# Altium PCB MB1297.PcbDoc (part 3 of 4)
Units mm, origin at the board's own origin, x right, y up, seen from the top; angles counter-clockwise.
Board outline 90.1 x 62.11 mm, 4 copper layers (Top Layer, GND, POWER+GND, Bottom Layer), stack 0.778 mm thick; 235 components, 174 nets, 1727 pads, 1 vias.
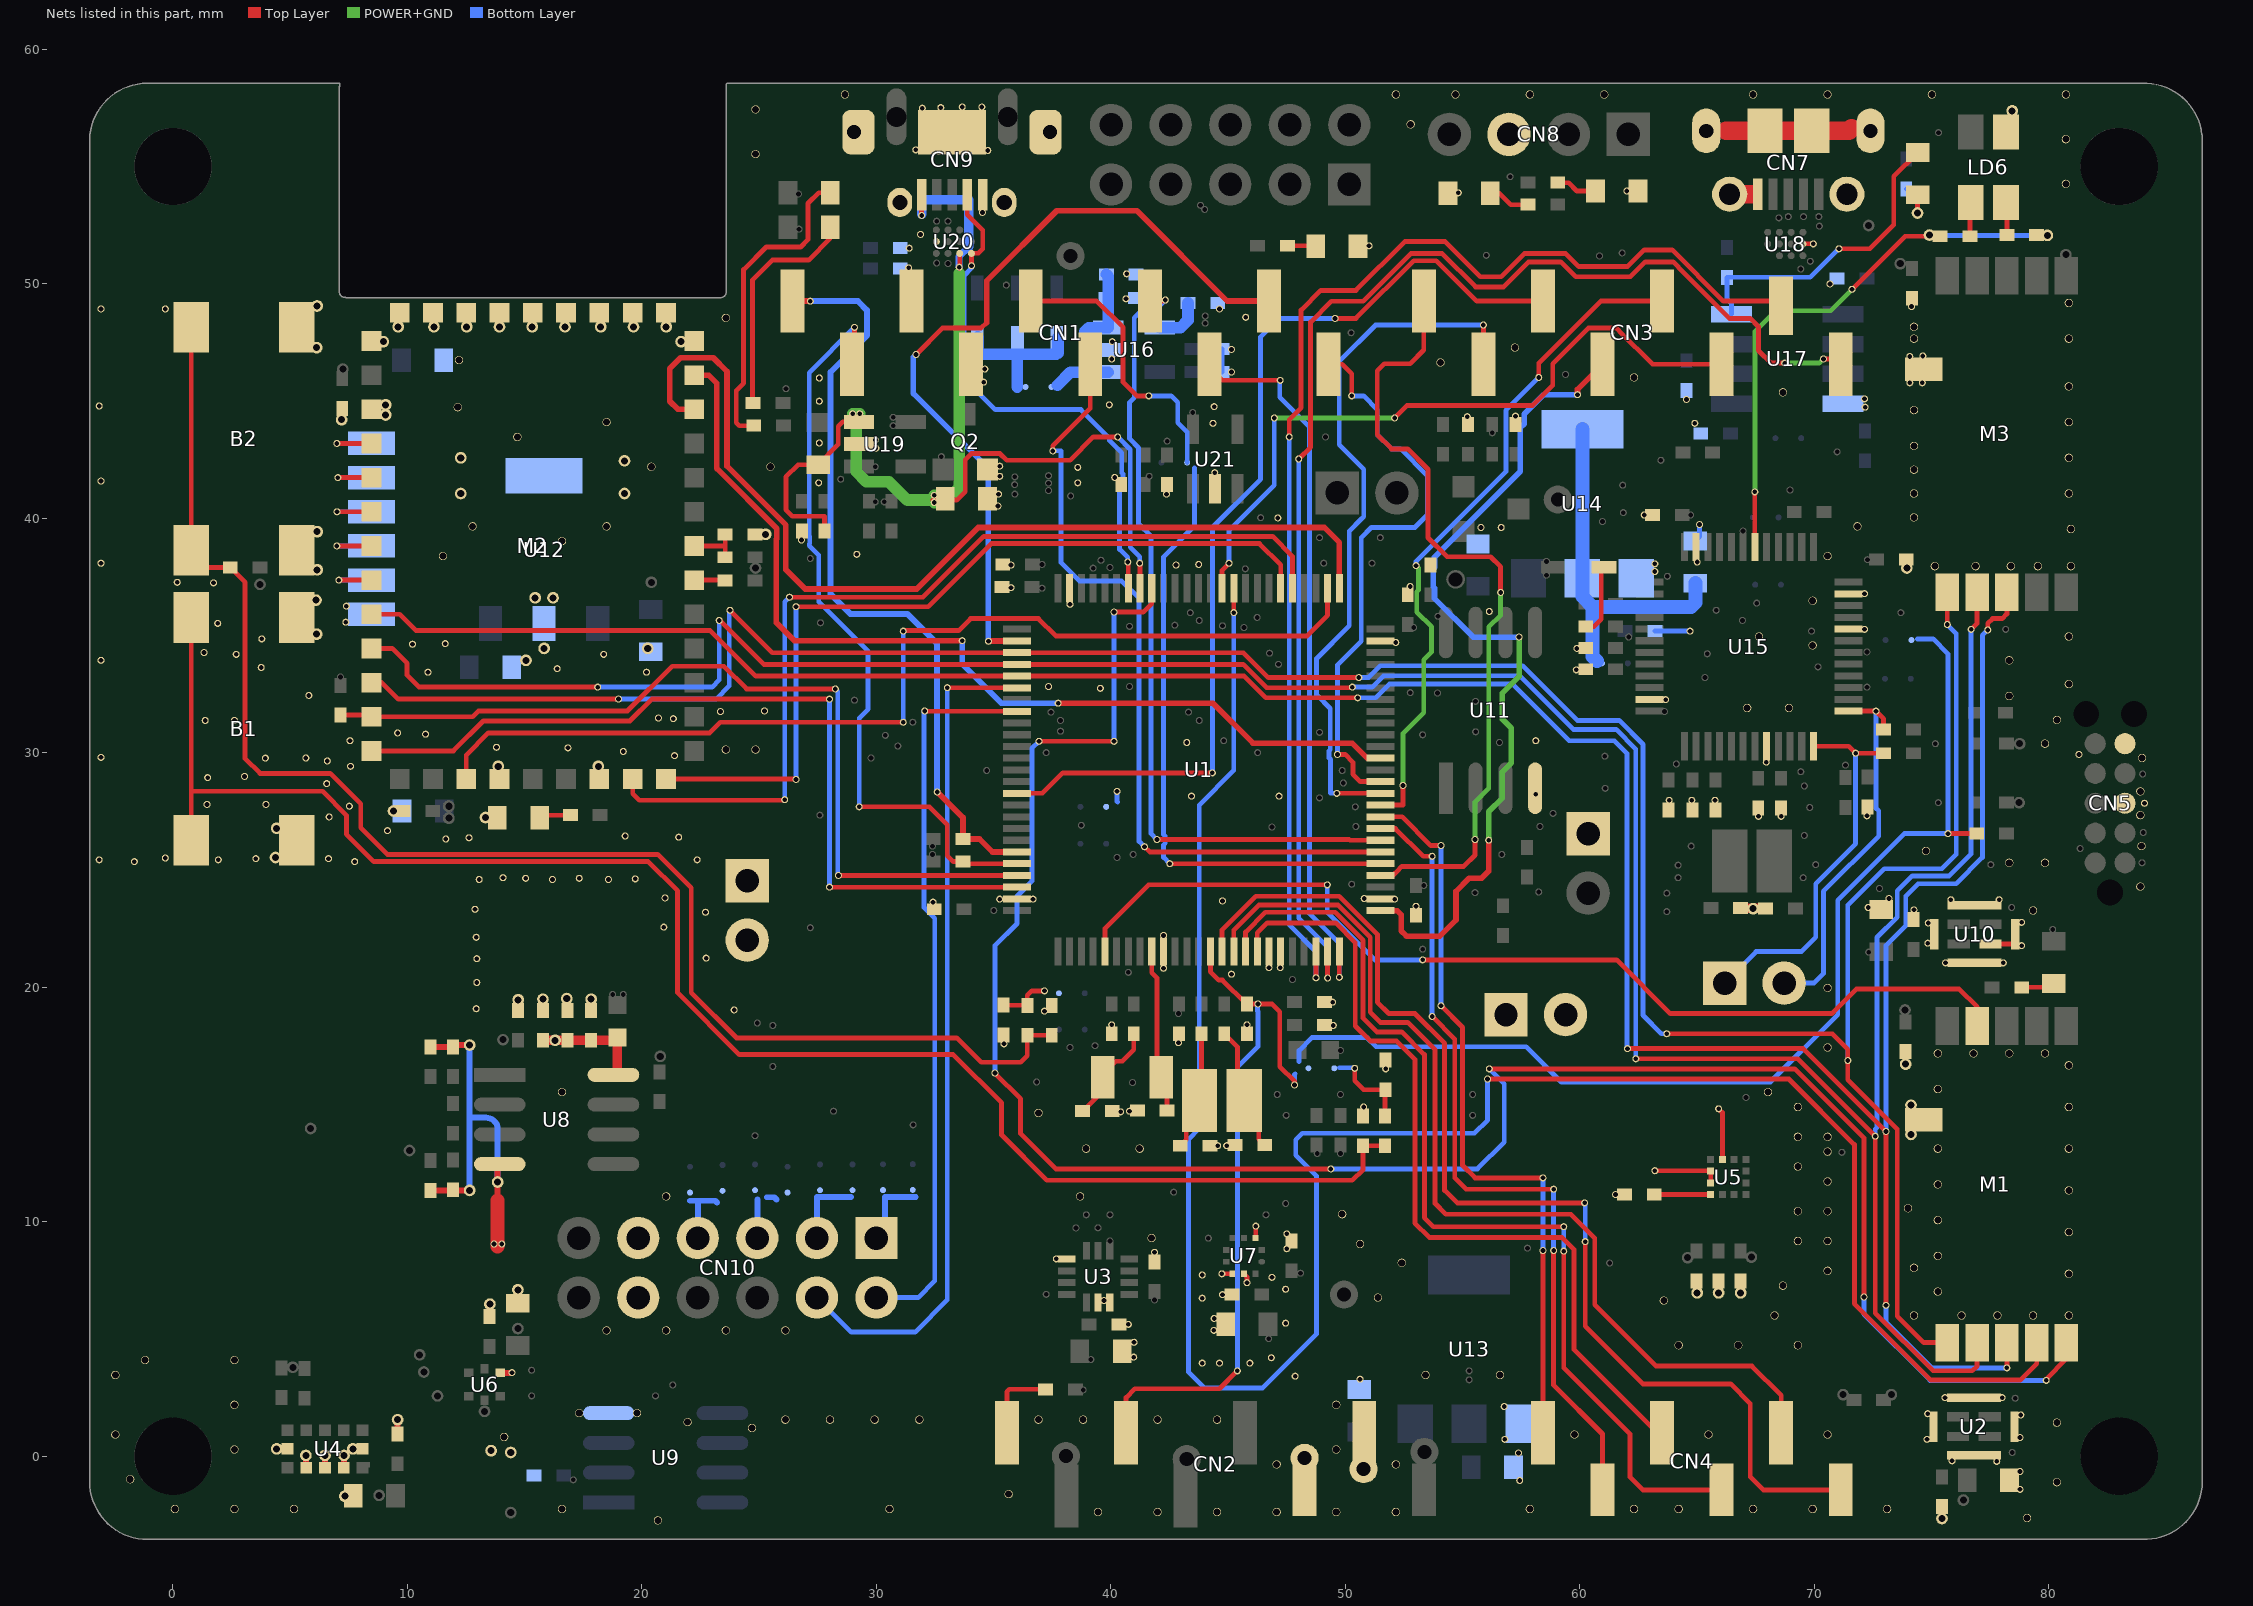
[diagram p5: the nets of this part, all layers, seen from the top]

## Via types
v1: diameter 0.4, hole 0.2, Top Layer to Bottom Layer, tented both sides, 1 vias

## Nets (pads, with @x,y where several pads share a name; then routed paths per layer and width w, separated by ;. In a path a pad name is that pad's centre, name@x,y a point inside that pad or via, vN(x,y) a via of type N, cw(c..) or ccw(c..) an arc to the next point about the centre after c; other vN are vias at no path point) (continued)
GND: B1.2 B2.2 C1.2 C2.2 C3.1 C4.2 C5.2 C6.1 C7.2 C8.1 C9.2 C10.2 C11.2 C12.2 C13.2 C14.2 C15.2 C16.2 C17.1 C18.2 C19.2 C20.2 C21.2 C22.2 C23.2 C24.2 C25.2 C26.2 C27.2 C28.2 C29.2 C30.2 C31.2 C32.2 C33.2 C34.2 C35.2 C36.2 C37.2 C38.2 C39.2 C40.2 C41.2 C42.2 C43.2 C44.2 C45.2 C46.2 C47.2 C48.2 C49.2 C50.2 C51.1 C52.1 C53.2 C54.2 C55.2 C56.2 C57.2 C58.2 C59.2 C60.2 C61.2 C62.2 C63.2 C64.2 C65.2 C66.2 C67.2 C68.2 C69.2 C71.2 C72.2 C73.2 C74.2 C75.2 C76.2 CN1.7 CN2.6 CN2.7 CN5.3 CN5.5 CN7.5 CN7.6 CN7.7 CN7.8 CN7.9 CN7.10 CN7.11 CN8.3 CN9.5 CN9.6 CN9.7 CN9.8 CN9.9 CN9.10 CN10.5 CN10.11 JP6.1 JP6.2 JP7.1 JP7.2 JP8.1 LD1.K LD2.K LD3.K LD5.K LD6.1 M1.6 M2.1 M2.3 M2.17 M2.20 M2.35 M2.36 M2.37 M2.38 M2.39 M2.40 M2.41 M2.42 M2.43 M2.44 M3.6 pad.0@13.569,0.233 pad.0@-3.068,48.925 pad.1@14.407,0.157 pad.1@-0.325,48.925 pad.2@13.518,6.482 pad.2@14.712,7.091 pad.2@-3.144,25.43 pad.3@13.328,27.234 pad.3@-0.325,25.506 pad.4@-1.646,25.354 pad.5@7.333,-1.71 pad.5@63.658,32.263 pad.5@-3.068,29.799 pad.6@7.397,36.251 pad.6@15.829,34.447 pad.6@72.141,36.784 pad.6@-3.068,33.939 pad.7@7.371,35.565 pad.7@7.673,0.31 pad.7@15.448,36.606 pad.7@72.141,35.26 pad.7@-3.068,38.079 pad.8@7.295,0.03 pad.8@16.21,36.606 pad.8@31.882,52.1 pad.8@67.95,29.596 pad.8@-3.068,41.585 pad.9@6.482,0.03 pad.9@12.273,42.575 pad.9@-3.144,44.785 pad.10@1.732,37.241 pad.10@5.669,0.03 pad.10@12.273,41.051 pad.10@65.004,38.13 pad.11@0.183,37.267 pad.11@4.425,0.31 pad.11@19.258,42.448 pad.11@62.743,40.137 pad.12@1.91,35.514 pad.12@9.581,1.554 pad.12@19.258,41.051 pad.13@1.478,28.935 pad.14@3.053,28.986 pad.15@1.377,31.374 pad.15@59.873,34.447 pad.15@69.957,51.7 pad.16@2.621,31.374 pad.16@8.971,47.528 pad.16@59.848,33.533 pad.17@1.326,34.269 pad.17@9.606,48.163 pad.18@2.698,34.193 pad.18@11.13,48.163 pad.19@6.558,28.681 pad.19@12.527,48.163 pad.19@74.148,49.027 pad.20@7.524,27.716 pad.20@13.924,48.163 pad.21@1.936,25.43 pad.21@15.321,48.163 pad.22@3.536,25.481 pad.22@16.718,48.163 pad.23@1.453,27.792 pad.23@18.242,48.163 pad.24@3.968,27.792 pad.24@12.654,17.531 pad.24@19.639,48.163 pad.25@6.66,27.259 pad.25@12.654,11.333 pad.25@21.036,48.163 pad.26@6.635,25.481 pad.26@13.848,11.689 pad.26@21.671,47.528 pad.27@7.752,25.354 pad.27@14.725,19.461 pad.28@13.061,24.592 pad.28@15.779,19.487 pad.28@25.278,39.311 pad.29@12.934,19.08 pad.29@16.795,19.512 pad.29@31.4,51.516 pad.30@12.959,20.198 pad.30@17.836,19.487 pad.31@12.959,21.214 pad.32@12.934,22.128 pad.33@12.883,23.322 pad.34@14.077,24.668 pad.35@15.042,24.643 pad.36@16.185,24.592 pad.37@17.328,24.643 pad.37@44.735,7.777 pad.38@18.573,24.592 pad.38@45.801,7.396 pad.39@19.716,24.617 pad.39@75.443,-2.662 pad.40@20.935,22.56 pad.41@20.986,23.805 pad.41@46.182,9.809 pad.42@9.149,26.675 pad.43@11.638,26.319 pad.43@44.76,6.888 pad.44@12.629,26.37 pad.44@44.404,5.872 pad.45@19.284,26.446 pad.45@44.392,5.364 pad.45@50.78,14.889 pad.45@84.079,27.843 pad.46@21.57,26.395 pad.46@51.72,16.515 pad.46@81.285,29.926 pad.47@22.357,25.43 pad.48@22.713,23.195 pad.48@48.264,-0.072 pad.48@50.779,-0.555 pad.49@22.738,21.239 pad.50@23.932,19.029 pad.50@40.988,4.856 pad.51@13.797,30.231 pad.51@40.975,4.221 pad.52@16.845,30.205 pad.52@40.747,5.618 pad.53@19.208,30.053 pad.54@21.392,29.875 pad.54@41.864,8.692 pad.55@20.706,31.475 pad.55@39.705,6.634 pad.55@40.264,28.351 pad.56@14.458,3.561 pad.56@21.341,31.45 pad.56@74.122,14.965 pad.57@14.026,9.047 pad.57@23.348,31.755 pad.57@37.673,8.412 pad.57@74.122,13.721 pad.58@13.696,9.047 pad.58@25.227,31.78 pad.58@73.894,16.718 pad.59@20.198,33.431 pad.59@51.008,51.618 pad.59@74.072,46.893 pad.60@16.388,33.584 pad.60@74.63,46.919 pad.61@18.369,34.193 pad.61@50.805,23.779 pad.61@74.072,45.776 pad.62@10.876,33.431 pad.62@52.101,23.754 pad.62@74.605,45.776 pad.63@11.613,34.65 pad.63@53.015,23.449 pad.63@64.547,45.064 pad.64@10.216,34.625 pad.64@40.671,50.424 pad.64@58.12,30.51 pad.64@64.902,44.048 pad.65@3.942,29.768 pad.65@40.645,49.357 pad.65@58.12,28.224 pad.65@72.141,45.09 pad.66 pad.67@5.796,32.441 pad.67@45.141,46.233 pad.68@3.764,33.634 pad.69@3.79,34.854 pad.69@46.741,20.833 pad.69@52.151,34.701 pad.70@6.584,29.647 pad.70@56.8,0.716 pad.70@65.004,6.964 pad.71@7.574,29.418 pad.71@56.774,2.113 pad.71@65.918,6.964 pad.72@7.549,30.51 pad.72@57.384,0.132 pad.72@66.858,6.964 pad.73@9.581,30.84 pad.73@57.435,-1.037 pad.74@10.775,30.79 pad.74@56.647,39.603 pad.75@39.553,32.745 pad.75@55.784,39.603 pad.76@37.343,32.822 pad.76@72.294,23.398 pad.77@73.183,23.779 pad.78@74.249,23.297 pad.80@74.859,22.738 pad.81@73.945,37.876 pad.81@74.84,21.874 pad.82@31.958,57.485 pad.82@67.391,23.347 pad.82@75.824,23.728 pad.83@32.746,57.51 pad.83@77.882,23.728 pad.84@7.193,44.201 pad.84@34.498,57.536 pad.84@78.84,22.763 pad.85@9.073,44.836 pad.85@34.752,55.682 pad.85@78.84,21.773 pad.86@9.073,44.404 pad.86@31.679,55.707 pad.86@75.596,21.036 pad.87@33.66,57.536 pad.87@78.059,21.036 pad.88@15.055,33.939 pad.88@34.524,53.04 pad.89@20.249,34.447 pad.89@34.625,46.36 pad.89@75.57,2.494 pad.90@34.575,45.801 pad.90@78.009,2.494 pad.91@9.403,27.513 pad.91@63.2,12.171 pad.91@78.807,1.757 pad.92@13.874,29.418 pad.92@65.918,14.813 pad.92@78.771,0.792 pad.93@18.141,29.418 pad.93@35.438,17.582 pad.94@4.425,26.776 pad.94@37.165,18.979 pad.95@4.374,25.532 pad.95@74.834,1.808 pad.96 pad.97@6.127,35.057 pad.97@38.258,36.327 pad.97@75.875,-0.198 pad.98 pad.99@6.152,37.8 pad.99@78.771,-0.656 pad.100 pad.101@6.127,47.274 pad.101@50.627,3.281 pad.105@47.452,7.117 pad.106@47.452,5.669 pad.106@72.243,27.31 pad.107@46.868,7.625 pad.107@67.62,27.284 pad.107@78.44,57.37 pad.108@43.896,7.726 pad.108@68.585,27.284 pad.109@43.896,6.736 pad.109@65.766,27.97 pad.110@43.896,3.967 pad.110@64.775,27.97 pad.111@44.633,3.967 pad.111@63.81,27.97 pad.112@42.245,22.204 pad.112@45.928,3.967 pad.113@42.245,20.807 pad.113@46.843,4.196 pad.114 pad.115@45.141,20.553 pad.115@49.459,19.36 pad.116@44.76,23.678 pad.116@49.484,18.369 pad.117@47.173,28.148 pad.118 pad.119 pad.120 pad.121@40.036,18.394 pad.121@43.744,38.029 pad.122 pad.123 pad.124 pad.125 pad.126@44.354,44.048 pad.126@54.818,53.878 pad.127 pad.128@35.743,37.038 pad.128@45.751,48.57 pad.129@27.564,45.979 pad.130@27.564,44.988 pad.131@27.564,43.21 pad.132@27.539,41.508 pad.133@29.164,38.46 pad.136@35.26,23.754 pad.137@36.683,23.754 pad.142 pad.143@52.761,37.089 pad.149@61.524,11.155 pad.173 pad.175 pad.217 pad.218 pad.219 pad.222 pad.225 pad.226 pad.231 pad.232 pad.233 pad.234 pad.235 pad.236 pad.237 pad.249 pad.250 pad.251 pad.252 pad.253 pad.254 pad.255 pad.256 pad.257 pad.258 pad.259 pad.260 pad.261 pad.262 pad.263 pad.264 pad.265 pad.266 pad.267 pad.268 pad.269 pad.270 pad.271 pad.272 pad.273 pad.274 pad.275 pad.276 pad.277 pad.278 pad.279 pad.280 pad.281 pad.282 pad.283 pad.284 pad.285 pad.286 pad.287 pad.288 pad.289 pad.290 pad.291 pad.292 pad.293 pad.294 pad.295 pad.296 pad.297 pad.298 pad.299 pad.300 pad.301 pad.302 pad.303 pad.304 pad.305 pad.306 pad.307 pad.308 pad.309 pad.310 pad.311 pad.312 pad.313 pad.314 pad.315 pad.316 pad.317 pad.318 pad.319 pad.320 pad.321 pad.322 pad.327 pad.328 pad.329 pad.330 pad.331 pad.332 pad.333 pad.334 pad.335 pad.336 pad.337 pad.338 pad.339 pad.340 pad.341 pad.342 pad.343 pad.344 pad.345 pad.346 pad.347 pad.348 pad.349 pad.350 pad.351 pad.352 pad.353 pad.354 pad.355 pad.356 pad.357 pad.358 pad.359 pad.360 pad.361 pad.362 pad.363 pad.364 pad.365 pad.366 pad.367 pad.368 pad.369 pad.370 pad.371 pad.372 pad.373 pad.374 pad.375 pad.376 pad.377 pad.378 pad.379 pad.380 pad.381 pad.382 pad.383 pad.384 pad.385 pad.386 pad.387 pad.388 pad.389 pad.390 pad.391 pad.392 pad.393 pad.394 pad.395 pad.396 pad.397 pad.398 pad.399 pad.400 pad.401 pad.402 pad.403 pad.404 pad.405 pad.406 pad.407 pad.408 pad.409 pad.410 pad.411 pad.412 pad.413 pad.414 pad.415 pad.416 pad.417 pad.418 pad.420 pad.421 pad.422 pad.423 pad.424 pad.425 pad.426 pad.427 pad.428 pad.429 pad.430 pad.431 pad.432 pad.433 pad.434 Q2.2 R1.1 R27.2 R29.2 R31.2 R36.2 R38.1 R41.2 R46.1 R53.1 R54.2 R59.1 R64.2 SB13.1 TP6.1 U1.10 U1.19 U1.20 U1.27 U1.49 U1.74 U1.99 U2.5 U3.1 U3.6 U3.7 U4.2 U4.3 U4.4 U4.6 U4.12 U5.2 U5.3 U5.12 U6.5 U7.3 U7.8 U7.9 U8.4 U9.4 U10.2 U10.5 U11.4 U12.2 U13.1 U14.1 U15.8 U15.20 U15.23 U15.35 U15.47 U16.2 U17.4 U18.D2 U19.2 U20.D2 U21.2 | length 39.4
  Top Layer w0.2: U10.2@77.515,21.841 78.499,21.841 78.542,21.798 U10.5@78.542,21.841
  Top Layer w0.204: pad.37@44.735,7.777 U7.8@45.174,7.777 ; U7.9@45.674,7.777 45.801,7.65 pad.38@45.801,7.396 ; U7.3@46.174,9.302 pad.41@46.174,9.801 ; pad.91@63.2,12.171 65.579,12.171 U5.3@65.579,11.654 ; pad.92@65.918,14.813 66.079,14.653 U5.12@66.079,12.654 ; U18.D2@69.526,51.701 pad.15@69.894,51.701
  Top Layer w0.254: pad.11@4.425,0.31 U4.6@4.882,0.31 ; U4.4@5.669,-0.478 pad.10@5.669,0.03 ; U4.3@6.482,-0.49 pad.9@6.482,0.03 ; U4.2@7.295,-0.478 pad.8@7.295,0.03 ; pad.7@7.673,0.31 U4.12@8.082,0.31 ; C22.2@9.581,0.945 pad.12@9.581,1.554 ; C72.2@10.978,11.333 pad.25@12.654,11.333 ; C69.2@10.978,17.455 C53.2@11.943,17.455 12.019,17.531 pad.24@12.654,17.531 ; pad.0@13.569,0.233 pad.0@13.574,0.228 ; 13.848,10.901 pad.26@13.848,11.689 13.848,12.234 cw(c14.154,12.234) U8.4@13.938,12.451 ; U6.5@13.964,3.553 14.45,3.553 pad.56@14.458,3.561
  Top Layer w0.4: C52.1@66.858,23.373 67.899,23.373 C51.1@67.925,23.347
  Top Layer w0.6: 13.848,8.946 13.848,10.901
  Top Layer w0.8: 66.248,56.52 71.481,56.52 71.582,56.621 ; CN7.7@66.39,53.818 67.341,53.818
  Bottom Layer w0.204: pad.55@40.264,28.351 40.264,27.919 40.29,27.894 ; C55.2@44.735,46.233 C59.2@44.735,47.223 ; C42.2@63.2,35.184 pad.222@64.699,35.184 ; C41.2@64.928,39.032 65.105,39.21 pad.217@65.105,39.73
  Bottom Layer w0.254: pad.25@12.654,11.333 12.654,14.432 ; pad.24@12.654,17.531 12.654,14.432 ; pad.26@13.848,11.689 13.848,13.973 ccw(c13.415,13.973) 13.721,14.28 ccw(c13.353,13.912) 13.353,14.432 12.654,14.432
LDO_3V3: C41.1 SB4.1 U14.2 U14.4 | length 15.4
  Bottom Layer w0.6: U14.4@60.106,43.794 U14.2@60.106,37.444 60.106,36.653 60.541,36.217 ; 60.737,33.914 60.541,34.109 60.541,36.217 ; C41.1@64.928,37.228 64.928,36.403 64.742,36.217 60.541,36.217
LED_STLINK: pad.18@67.464,41.123 pad.110@74.91,52.075 pad.111@79.939,52.062 pad.238 R44.1 R47.1 U15.30 | length 23.3
  Top Layer w0.204: U15.30@67.464,38.773 pad.18@67.464,41.123 ; pad.238@71.608,49.763 73.872,52.027 74.862,52.027 pad.110@74.91,52.075
  POWER+GND w0.204: pad.18@67.468,41.178 67.468,47.96 68.357,48.849 70.693,48.849 pad.238@71.608,49.763
  Bottom Layer w0.204: pad.110@74.91,52.075 74.923,52.062 pad.111@79.939,52.062
NetB1_1: B1.1 C35.1 R19.2 | length 73.2
  Top Layer w0.204: B1.1@0.778,26.268 0.778,28.351 ; B1.1@1.438,36.428 B1.1@0.778,35.768 0.778,28.351 ; R19.2@51.694,13.238 C35.1@50.754,13.238 50.754,12.222 50.297,11.765 37.267,11.765 35.337,13.695 35.337,15.067 33.279,17.124 24.161,17.124 21.519,19.766 21.519,24.109 20.274,25.354 8.565,25.354 7.397,26.522 7.397,27.335 6.381,28.351 0.778,28.351
NetB2_1: B2.1 C37.1 R23.1 R24.2 | length 63.9
  Top Layer w0.204: B2.1@0.778,48.138 B2.1@0.778,38.638 1.514,37.902 R23.1@2.444,37.902 3.079,37.267 3.079,29.748 3.714,29.113 6.711,29.113 8.006,27.818 8.006,26.802 9.148,25.66 20.68,25.66 22.103,24.236 22.103,19.766 24.034,17.836 33.432,17.836 34.473,16.794 36.149,16.794 36.438,17.082 R24.2@36.438,17.952 C37.1@37.479,17.952
NetC2_1: C2.1 R5.2 X1.2 | length 5.3
  Top Layer w0.204: C2.1@42.957,13.238 43.211,13.492 43.211,14.595 X1.2@43.785,15.169 ; X1.2@43.505,15.143 43.871,15.509 R5.2@43.871,18.013
NetC3_2: C3.2 CN2.3 pad.35@45.395,3.637 pad.36@46.271,19.283 pad.43@47.833,15.829 pad.72@75.697,26.548 R34.2 SB2.1 SB8.1 U1.14 | length 78
  Top Layer w0.204: CN2.3@40.646,1.001 40.646,2.495 41.026,2.875 44.633,2.875 pad.35@45.395,3.637 ; U1.14@44.244,21.516 44.244,20.663 44.606,20.301 44.76,20.301 45.777,19.283 C3.2@45.801,19.283 pad.36@46.271,19.283 46.868,19.283 47.199,18.952 47.199,16.616 47.833,15.981 pad.43@47.833,15.829 ; pad.72@75.697,26.548 R34.2@76.929,26.548
  Bottom Layer w0.204: pad.35@45.395,3.637 45.395,16.591 46.271,17.467 46.271,18.962 46.256,18.977 46.256,19.268 pad.36@46.271,19.283 ; pad.43@47.833,15.829 47.833,16.286 47.859,16.312 ; 48.024,16.82 48.024,17.298 48.574,17.849 50.919,17.849 51.312,17.456 57.712,17.456 59.213,15.956 68.128,15.956 70.998,18.826 70.998,23.71 73.836,26.548 pad.72@75.697,26.548 75.697,34.219 75.062,34.854 74.402,34.854
NetC4_1: C4.1 R7.2 X1.1 | length 5.4
  Top Layer w0.204: R7.2@44.836,18.013 45.405,17.444 X1.1@45.405,15.143 ; X1.1@45.685,15.169 46.309,14.544 46.309,13.518 C4.1@46.563,13.264
NetC14_1: C14.1 R12.2 X2.1 | length 4.4
  Top Layer w0.204: C14.1@38.791,14.711 39.649,15.57 X2.1@39.649,16.159 39.649,16.281 40.213,16.845 40.493,16.845 40.975,17.328 R12.2@40.975,18.013
NetC15_1: C15.1 U1.9 X2.2 | length 7
  Top Layer w0.204: U1.9@41.744,21.516 41.744,20.623 41.966,20.401 41.966,18.039 41.966,16.342 X2.2@42.149,16.159 42.398,15.911 C15.1@42.398,14.737
NetC23_1: C23.1 U5.4 | length 2.4
  Top Layer w0.204: C23.1@63.176,11.154 U5.4@65.579,11.154
NetC32_1: C32.1 C67.1 C68.1 L2.1 pad.31@16.299,17.734 U8.8 | length 4.6
  Top Layer w0.4: C67.1@15.779,17.734 C68.1@16.82,17.734 C32.1@17.836,17.734 18.839,17.734 L2.1@18.954,17.848 U8.8@18.954,16.427
NetC34_1: C34.1 pad.44@50.399,16.54 R19.1 SB2.2 | length 3.8
  Top Layer w0.204: pad.44@50.399,16.54 50.399,16.007 50.78,15.626 C34.1@51.72,15.626 51.694,15.6 R19.1@51.694,14.508
  Bottom Layer w0.204: 49.738,16.566 50.373,16.566 pad.44@50.399,16.54
NetC36_1: C36.1 pad.47@37.165,19.842 R24.1 SB3.2 | length 2.3
  Top Layer w0.204: C36.1@35.413,19.233 36.427,19.233 R24.1@36.438,19.222 36.438,19.648 36.632,19.842 pad.47@37.165,19.842
NetC56_1: C56.1 C57.1 SB10.1 U16.1 U16.3 | length 7.5
  Bottom Layer w0.5: 37.724,45.674 38.276,46.226 38.893,46.226 ; C56.1@39.807,50.398 39.893,50.312 U16.3@39.893,48.126 39.058,48.126 38.891,47.959 38.891,46.729 38.893,46.728 38.893,46.226 ; U16.1@39.893,46.226 38.893,46.226
NetC58_1: C58.1 U16.4 | length 2.1
  Bottom Layer w0.5: U16.4@42.093,48.126 42.97,48.126 43.287,48.443 C58.1@43.287,49.179
NetC66_1: C66.1 CN9.1 pad.0@31.928,52.913 pad.4@33.533,50.703 pad.20@29.291,44.455 pad.21@32.466,40.975 pad.22@32.466,40.67 pad.126@28.987,44.455 pad.179 pad.181 R57.1 R61.2 U1.68 U19.1 U20.B3 | length 49.7
  Top Layer w0.2: pad.4@33.555,50.648 U20.B3@33.555,51.295
  Top Layer w0.204: R57.1@27.788,39.451 27.788,40.086 26.421,40.086 26.142,40.365 26.142,41.762 26.663,42.283 R61.2@27.513,42.283 28.377,43.147 28.377,43.921 28.565,44.109 U19.1@29.258,44.109 ; pad.0@31.928,52.964 CN9.1@31.928,53.792 ; pad.22@32.416,40.772 33.432,40.772 33.787,41.127 33.787,42.499 34.047,42.758 35.272,42.758 35.557,42.474 38.258,42.474 39.248,43.464 pad.181@40.29,43.464 ; pad.179@41.229,38.079 41.244,38.065 U1.68@41.244,37.016
  POWER+GND w0.5: pad.126@28.987,44.455 pad.20@29.291,44.455 29.139,44.302 29.139,41.991 29.571,41.559 30.536,41.559 31.323,40.772 pad.22@32.466,40.772 ; pad.22@32.466,40.67 pad.22@32.466,40.772 ; pad.21@32.466,40.975 pad.22@32.466,40.772 ; 33.533,50.446 33.533,41.305 33,40.772 pad.22@32.466,40.772
  Bottom Layer w0.204: pad.181@40.29,43.464 40.824,42.93 40.824,41.567 40.823,41.566 40.823,38.765 41.229,38.359 pad.179@41.229,38.079
  Bottom Layer w0.3: pad.4@33.524,50.703 33.524,51.154 33.94,51.57
  Bottom Layer w0.4: pad.0@31.928,52.964 31.928,53.573 33.94,53.573 33.94,51.57
NetCN1_1: CN1.1 pad.58@50.272,45.217 pad.141@49.662,29.926 U1.37 | length 24.5
  Top Layer w0.204: CN1.1@49.282,46.561 49.867,46.561 50.272,46.157 pad.58@50.272,45.217 ; pad.141@49.662,29.926 49.992,29.926 50.323,29.596 50.323,29.088 50.645,28.766 U1.37@51.494,28.766
  Bottom Layer w0.204: pad.141@49.662,29.926 49.662,33.736 50.678,34.752 50.678,39.172 51.11,39.603 52.964,39.603 53.498,40.137 53.498,41.813 52.355,42.956 51.974,42.956 51.364,43.566 51.364,44.633 50.78,45.217 pad.58@50.272,45.217
NetCN1_2: CN1.2 pad.27@31.691,46.982 pad.95@34.778,34.752 U1.77 | length 35.1
  Top Layer w0.204: pad.27@31.691,46.982 32.825,48.115 34.476,48.115 34.702,48.341
  Top Layer w0.24: 34.702,48.341 34.702,50.119 37.694,53.112 41.107,53.112 44.957,49.261 CN1.2@46.742,49.261 ; pad.95@34.778,34.752 34.791,34.766 U1.77@35.994,34.766
  Bottom Layer w0.24: pad.27@31.691,46.982 31.577,46.868 31.577,45.318 34.778,42.118 pad.95@34.778,34.752
NetCN1_3: CN1.3 pad.23@47.222,45.879 pad.72@49.744,20.421 U1.25 | length 30.9
  Top Layer w0.204: CN1.3@44.202,46.435 44.758,45.879 pad.23@47.222,45.879 ; pad.72@49.744,20.421 U1.25@49.744,21.516
  Bottom Layer w0.204: pad.23@47.222,45.879 47.198,45.855 47.198,45.166 48.468,43.896 48.468,23.144 49.744,21.869 pad.72@49.744,20.421
NetCN1_4: CN1.4 pad.63@42.322,49.306 pad.83@41.966,26.295 U1.32 | length 34.7
  Top Layer w0.204: CN1.4@41.662,49.261 42.277,49.261 pad.63@42.322,49.306 ; pad.83@41.966,26.295 50.163,26.295 50.193,26.266 U1.32@51.494,26.266
  Bottom Layer w0.204: pad.83@41.966,26.295 41.712,26.549 41.712,39.222 41.179,39.756 41.179,43.008 40.798,43.389 40.798,44.937 41.001,45.141 41.001,48.544 41.233,48.776 41.792,48.776 pad.63@42.322,49.306
NetCN1_5: CN1.5 pad.38@37.525,42.868 pad.73@41.433,25.989 U1.31 | length 34.3
  Top Layer w0.204: pad.38@37.525,42.868 37.525,43.088 39.122,44.684 CN1.5@39.122,46.561 ; pad.73@41.433,25.989 41.656,25.766 U1.31@51.494,25.766
  Bottom Layer w0.204: pad.38@37.525,42.868 37.877,42.88 37.877,38.105 38.664,37.317 40.467,37.317 41.204,36.581 41.204,26.218 pad.73@41.433,25.989
NetCN1_6: CN1.6 pad.84@42.512,25.266 pad.171 SB1.1 U1.30 | length 38.7
  Top Layer w0.204: CN1.6@36.582,49.261 39.395,49.261 40.518,48.138 40.518,45.801 41.102,45.217 pad.171@41.619,45.217 ; pad.84@42.512,25.266 U1.30@51.494,25.266
  Bottom Layer w0.204: pad.171@41.619,45.217 42.576,45.217 42.855,44.937 42.855,44.074 43.253,43.675 SB1.1@43.253,42.372 ; pad.84@42.512,25.266 42.245,25.532 42.245,26.074 42.32,26.148 42.32,26.442 42.245,26.516 42.245,38.359 43.566,39.68 43.566,42.143
NetCN1_8: CN1.8 pad.28@31.374,50.678 R2.1
NetCN1_9: CN1.9 pad.108@29.266,27.691 pad.110@29.063,48.138 R8.2 U1.96 | length 32.6
  Top Layer w0.204: CN1.9@28.962,46.561 29.063,46.662 pad.110@29.063,48.138 ; pad.108@29.266,27.691 32.263,27.691 33.025,26.929 33.025,25.608 33.279,25.354 R8.2@33.686,25.354 ; R8.2@33.774,25.266 U1.96@35.994,25.266
  Top Layer w0.254: R8.2@33.686,25.354 R8.2@33.774,25.266
  Bottom Layer w0.204: pad.110@29.063,48.138 27.132,46.207 27.132,39.24 27.156,39.217 27.156,38.923 27.132,38.9 27.132,38.834 27.537,38.429 27.537,36.43 29.647,34.32 29.647,31.856 29.266,31.475 pad.108@29.266,27.691
NetCN1_10: CN1.10 pad.109@32.593,28.326 pad.111@27.183,49.255 R9.2 U1.95 | length 32.8
  Top Layer w0.254: CN1.10@26.422,49.261 27.177,49.261 pad.111@27.183,49.255 ; pad.109@32.593,28.326 33.686,27.234 R9.2@33.686,26.319 34.397,26.319 34.95,25.766 U1.95@35.994,25.766
  Bottom Layer w0.254: pad.111@27.183,49.255 29.215,49.255 29.596,48.874 29.596,47.782 28.047,46.233 28.047,36.759 28.885,35.92 31.323,35.92 32.593,34.65 pad.109@32.593,28.326
NetCN2_1: CN2.1 R3.2 | length 3.4
  Top Layer w0.204: CN2.1@35.566,1.001 35.566,2.749 35.667,2.85 R3.2@37.216,2.85
NetCN3_1: CN3.1 pad.25@48.011,42.524 pad.67@68.738,46.614 pad.69@70.389,46.792 pad.71@49.244,20.389 U1.24 | length 57.4
  Top Layer w0.204: pad.25@48.011,42.524 48.519,43.032 48.519,48.366 49.408,49.255 50.754,49.255 52.786,51.287 54.133,51.287 55.555,49.865 56.749,49.865 57.816,50.932 59.186,50.932 59.821,50.297 62.159,50.297 62.794,50.932 63.984,50.932 64.22,50.696 64.22,50.674 66.375,48.519 67.264,48.519 67.62,48.163 67.62,47.147 68.153,46.614 pad.67@68.738,46.614 ; pad.71@49.244,20.389 U1.24@49.244,21.516 ; pad.69@70.389,46.792 CN3.1@70.896,46.792
  POWER+GND w0.204: pad.67@68.738,46.614 70.211,46.614 pad.69@70.389,46.792
  Bottom Layer w0.204: pad.25@48.011,42.524 48.011,22.941 49.244,21.708 pad.71@49.244,20.389
NetCN3_2: CN3.2 pad.24@47.605,43.464 pad.70@48.748,20.401 U1.23 | length 54.4
  Top Layer w0.204: pad.24@47.605,43.464 47.605,44.201 48.113,44.709 48.113,48.874 48.951,49.713 50.45,49.713 52.532,51.795 54.26,51.795 55.758,50.297 56.647,50.297 57.638,51.287 59.39,51.287 59.949,50.729 62.032,50.729 62.743,51.44 63.937,51.44 66.116,49.261 CN3.2@68.586,49.261 ; U1.23@48.744,21.516 48.744,20.405 pad.70@48.748,20.401
  Bottom Layer w0.204: pad.24@47.605,43.464 47.605,22.662 48.748,21.519 pad.70@48.748,20.401
NetCN3_3: CN3.3 pad.202 pad.203 pad.204 U1.61 | length 30
  Top Layer w0.204: U1.61@44.744,37.016 44.744,37.784 pad.202@45.039,38.079 ; pad.204@52.101,44.277 52.634,44.81 57.993,44.81 58.845,45.662 58.845,46.588 60.372,48.115 61.561,48.115 61.68,47.996 61.68,47.982 63.101,46.561 CN3.3@66.046,46.561
  POWER+GND w0.204: pad.203@46.97,44.277 pad.204@52.101,44.277
  Bottom Layer w0.204: pad.202@45.039,38.079 45.039,39.476 46.97,41.407 pad.203@46.97,44.277
NetCN3_4: CN3.4 pad.224 pad.229 pad.230 U1.35 | length 29.2
  Top Layer w0.204: U1.35@51.494,27.766 52.458,27.766 pad.229@52.458,28.604 ; pad.224@58.247,46.004 58.247,46.614 60.895,49.261 CN3.4@63.506,49.261
  POWER+GND w0.204: pad.229@52.458,28.604 52.458,30.816 53.345,31.704 53.345,33.965 53.675,34.295 53.675,35.362 53.04,35.997 53.04,36.868 53.115,36.942 53.115,37.878 pad.230@53.015,37.978
  Bottom Layer w0.204: pad.230@53.015,37.952 pad.230@53.015,37.978 53.015,38.156 56.85,41.991 56.85,44.607 pad.224@58.247,46.004
NetCN3_5: CN3.5 pad.52@56.114,26.268 pad.223 pad.228 U1.26 | length 36.3
  Top Layer w0.24: U1.26@51.494,23.266 52.208,23.266 52.38,23.093 52.38,22.408 52.609,22.179 54.031,22.179 54.717,22.865 54.717,24.084 55.276,24.643 55.809,24.643 56.114,24.948 pad.52@56.114,26.268 ; pad.223@59.898,45.268 59.898,45.493 CN3.5@60.966,46.561
  POWER+GND w0.24: pad.52@56.114,26.268 56.114,27.488 56.698,28.072 56.698,29.189 57.079,29.57 57.079,31.044 56.698,31.425 56.698,32.542 57.409,33.253 pad.228@57.409,34.93
  Bottom Layer w0.24: pad.228@57.409,34.93 55.453,34.93 53.802,36.581 53.802,37.019 53.752,37.07 53.752,37.844 53.802,37.895 53.802,38.333 57.46,41.991 57.46,43.862 57.629,44.03 57.629,44.446 58.451,45.268 pad.223@59.898,45.268
NetCN3_6: CN3.6 pad.65@44.328,29.139 pad.75@49.561,48.519 U1.90 | length 42.2
  Top Layer w0.204: U1.90@35.994,28.266 37.08,28.266 37.953,29.139 pad.65@44.328,29.139 ; pad.75@49.561,48.519 50.451,48.519 52.913,50.981 53.88,50.981 55.6,49.261 CN3.6@58.426,49.261
  Bottom Layer w0.204: pad.65@44.328,29.139 44.328,39.603 46.386,41.661 46.386,47.731 47.173,48.519 pad.75@49.561,48.519
NetCN3_7: CN3.7 pad.57@55.885,48.239 pad.140@49.637,28.266 U1.36 | length 30.6
  Top Layer w0.204: pad.140@49.637,28.266 U1.36@51.494,28.266 ; pad.57@55.885,48.239 pad.57@55.885,48.239 CN3.7@55.886,46.561
  Bottom Layer w0.204: pad.140@49.637,28.266 49.367,28.266 49.367,29.721 49.308,29.779 49.308,30.073 49.356,30.121 49.356,31.884 48.774,32.466 48.774,34.017 50.17,35.412 50.17,39.451 50.667,39.948 ; 50.668,39.948 50.787,40.067 50.787,42.086 49.738,43.135 49.738,46.69 51.288,48.239 pad.57@55.885,48.239
NetCN3_8: CN3.8 pad.54@55.53,26.294 pad.55@56.622,36.835 U1.29 | length 33.6
  Top Layer w0.204: U1.29@51.494,24.766 52.033,24.766 52.298,25.031 52.298,25.043 52.405,25.151 55.047,25.151 55.53,25.633 pad.54@55.53,26.294 ; CN3.8@53.346,49.261 53.346,47.174 52.761,46.588 51.669,46.588 51.364,46.284 51.364,43.566 51.974,42.956 52.659,42.956 53.524,42.091 53.524,39.17 54.336,38.359 56.19,38.359 56.622,37.927 pad.55@56.622,36.835
  POWER+GND w0.204: pad.54@55.53,26.294 55.53,27.894 56.114,28.478 56.114,35.362 56.622,35.87 pad.55@56.622,36.835
NetCN4_1: CN4.1 pad.77@58.426,8.768 pad.81@58.426,11.866 pad.88@54.082,26.04 pad.90@54.082,19.207 U1.34 | length 31.6
  Top Layer w0.204: U1.34@51.494,27.266 52.424,27.266 53.65,26.04 pad.88@54.082,26.04 ; pad.90@54.082,19.207 54.996,18.293 54.996,12.4 55.531,11.866 pad.81@58.426,11.866 ; CN4.1@58.426,1.001 pad.77@58.426,8.768
  Bottom Layer w0.204: pad.90@54.082,19.283 pad.88@54.082,26.04 ; pad.81@58.426,11.866 pad.81@58.426,11.866 pad.77@58.426,8.768
NetCN4_2: CN4.2 pad.78@58.882,8.768 pad.82@58.882,11.384 pad.87@53.701,25.583 pad.89@53.701,18.75 U1.33 | length 34.9
  Top Layer w0.204: U1.33@51.494,26.766 52.137,26.766 53.32,25.583 pad.87@53.701,25.583 ; pad.89@53.701,18.75 54.666,17.785 54.666,11.867 55.149,11.384 pad.82@58.882,11.384 ; pad.78@58.882,8.768 58.882,3.027 60.966,0.944 CN4.2@60.966,-1.439
  Bottom Layer w0.204: pad.89@53.701,18.75 pad.87@53.701,25.583 ; pad.78@58.882,8.768 pad.82@58.882,11.384 pad.82@58.908,11.384
NetCN4_3: CN4.3 U1.18 | length 35.9
  Top Layer w0.204: U1.18@46.244,21.516 46.244,22.317 46.665,22.738 49.586,22.738 50.424,21.9 50.424,18.344 51.059,17.709 52.177,17.709 52.964,16.921 52.964,9.936 53.574,9.327 59.238,9.327 59.746,8.819 59.746,4.551 63.296,1.001 CN4.3@63.506,1.001
NetCN4_4: CN4.4 pad.75@59.314,9.784 pad.76@59.314,8.742 U1.17 | length 42.3
  Top Layer w0.204: U1.17@45.744,21.516 45.744,22.35 46.588,23.194 49.563,23.194 50.754,22.002 50.754,18.674 51.339,18.09 52.405,18.09 53.371,17.124 53.371,10.165 53.752,9.784 pad.75@59.314,9.784 ; pad.76@59.314,8.742 59.314,3.764 62.134,0.945 62.134,-0.884 62.688,-1.439 CN4.4@66.046,-1.439
  Bottom Layer w0.204: pad.76@59.314,8.742 pad.75@59.314,9.784
NetCN4_5: CN4.5 U1.16 | length 42.3
  Top Layer w0.204: U1.16@45.244,21.516 45.244,22.434 46.309,23.5 49.69,23.5 51.06,22.129 51.06,18.927 51.491,18.496 52.659,18.496 53.828,17.328 53.828,10.774 54.285,10.317 59.619,10.317 60.635,9.301 60.635,6.456 63.251,3.84 67.341,3.84 68.586,2.595 CN4.5@68.586,1.001
NetCN4_6: CN4.6 pad.79@60.229,9.149 pad.80@60.203,10.8 U1.15 | length 48.7
  Top Layer w0.204: U1.15@44.744,21.516 44.744,22.442 46.182,23.881 49.741,23.881 51.366,22.256 51.366,19.357 51.847,18.877 52.964,18.877 54.234,17.607 54.234,11.333 54.768,10.8 pad.80@60.203,10.8 ; pad.79@60.229,9.149 60.229,5.542 62.692,3.078 66.426,3.078 67.264,2.24 67.264,-0.884 67.819,-1.439 CN4.6@71.126,-1.439
  Bottom Layer w0.204: pad.80@60.203,10.8 60.229,10.774 pad.79@60.229,9.149
NetCN6_1: CN6.1 pad.102@71.76,29.977 R42.1 U15.12 | length 16.4
  Top Layer w0.204: U15.12@69.964,30.273 71.464,30.273 pad.102@71.76,29.977 R42.1@72.954,29.977
  Bottom Layer w0.204: CN6.1@66.172,20.172 67.518,21.519 69.449,21.519 70.058,22.128 70.058,24.414 71.76,26.116 pad.102@71.76,29.977
NetCN6_2: CN6.2 pad.103@72.631,31.773 R43.1 U15.13 | length 16.1
  Top Layer w0.204: U15.13@71.464,31.773 pad.103@72.631,31.773 72.954,31.45 R43.1@72.954,30.993
  Bottom Layer w0.204: CN6.2@68.712,20.172 69.982,20.172 70.389,20.579 70.389,24.084 72.748,26.443 72.748,27.523 72.631,27.64 pad.103@72.631,31.773
NetCN9_4: CN9.4 pad.5@34.055,50.766 pad.180 U1.69 U20.A3 | length 22.7
  Top Layer w0.204: CN9.4@33.878,53.792 33.878,52.949 34.54,52.288 34.54,51.485 34.35,51.295 U20.A3@34.055,51.295 pad.5@34.055,50.766 ; pad.180@40.721,38.13 40.744,38.108 U1.69@40.744,37.016
  Bottom Layer w0.204: pad.5@34.055,50.766 34.055,50.666 33.736,50.348 33.736,45.961 35.065,44.633 38.723,44.633 39.936,43.42 39.936,43.318 40.467,42.786 40.467,41.933 40.517,41.884 40.517,41.59 40.373,41.446 40.373,38.657 40.391,38.657 40.721,38.326 pad.180@40.721,38.13
NetCN10_1: CN10.1 SB14.1 SB19.1 | length 3.2
  Bottom Layer w0.254: CN10.1@30.003,9.301 30.358,9.657 30.358,11.054 31.679,11.054
NetCN10_2: CN10.2 SB12.1 SB15.1 | length 3.8
  Bottom Layer w0.254: CN10.2@27.031,9.733 CN10.2@27.463,9.301 27.463,11.054 28.91,11.054
NetCN10_3: CN10.3 SB18.1 SB20.2 | length 2.1
  Bottom Layer w0.254: CN10.3@24.923,9.301 24.923,10.952 ; 25.325,11.041 25.646,11.041 25.735,10.952
NetCN10_4: CN10.4 SB16.1 SB21.2 | length 2.7
  Bottom Layer w0.254: 22.052,10.891 23.129,10.891 23.195,10.825 ; CN10.4@22.383,9.301 22.383,10.825
NetCN10_7: CN10.7 pad.143@32.06,31.78 U1.83 | length 31.2
  Top Layer w0.204: pad.143@32.045,31.766 U1.83@35.994,31.766
  Bottom Layer w0.204: CN10.7@30.003,6.761 31.781,6.761 32.492,7.472 32.492,22.941 32.035,23.398 32.035,31.755 pad.143@32.06,31.78
NetCN10_8: CN10.8 pad.144@33.025,32.771 U1.81 | length 35.8
  Top Layer w0.204: pad.144@33.025,32.771 33.03,32.766 U1.81@35.994,32.766
  Bottom Layer w0.204: CN10.8@27.463,6.761 28.936,5.288 31.654,5.288 33.025,6.66 pad.144@33.025,32.771
NetD2_2: D2.2 R28.1 | length 3
  Top Layer w0.204: R28.1@60.254,35.387 60.61,35.387 60.914,35.692 60.914,37.79 D2.2@61.026,37.902
NetD3_2: D3.2 D4.2 D5.2 SB10.2 | length 6.2
  Bottom Layer w0.5: D4.2@34.321,47.728 34.321,46.995 37.673,46.995 37.75,47.071 ; 36.007,45.598 36.007,46.954 ; 37.75,47.046 D3.2@37.75,47.703
NetLD1_A: LD1.A R18.2 | length 1.8
  Top Layer w0.204: LD1.A@56.177,53.853 56.571,53.853 57.054,53.37 R18.2@57.79,53.37
NetLD2_A: LD2.A R20.2 | length 1.8
  Top Layer w0.204: R20.2@59.06,54.31 59.517,54.31 59.873,53.954 LD2.A@60.673,53.954
NetLD3_A: LD3.A R21.2 | length 1.4
  Top Layer w0.204: LD3.A@15.639,27.234 15.741,27.335 R21.2@16.947,27.335
NetLD4_K: LD4.K R22.2 | length 1.4
  Top Layer w0.204: R22.2@78.847,19.995 80.053,19.995 LD4.K@80.218,20.16
NetLD5_A: LD5.A R25.2 | length 1.2
  Top Layer w0.204: R25.2@47.529,51.618 48.71,51.618 LD5.A@48.735,51.592
NetLD6_2: LD6.2 R44.2 | length 1.4
  Top Layer w0.204: LD6.2@78.174,53.47 78.212,53.433 R44.2@78.212,52.075
NetLD6_3: LD6.3 R47.2 | length 1.5
  Top Layer w0.204: R47.2@76.637,52.024 76.637,53.433 LD6.3@76.674,53.47
NetLD7_A: LD7.A pad.1@74.402,53.015 R52.1 | length 2
  Top Layer w0.204: pad.1@74.402,53.015 LD7.A@74.402,53.789
  Bottom Layer w0.204: R52.1@73.919,54.043 74.402,53.561 pad.1@74.402,53.015
NetLD7_K: LD7.K pad.74@71.049,51.491 R49.1 U17.8 | length 13.2
  Top Layer w0.204: pad.74@71.049,51.491 72.37,51.491 73.386,52.507 73.386,54.577 LD7.K@74.402,55.593
  Bottom Layer w0.204: U17.8@66.464,48.697 66.464,49.167 66.274,49.357 R49.1@66.274,50.271 69.83,50.271 pad.74@71.049,51.491
NetLD8_K: LD8.K R56.2 | length 9.8
  Top Layer w0.204: R56.2@24.745,44.912 24.719,44.937 24.719,50.17 25.556,51.006 27.105,51.006 28.034,51.935 LD8.K@28.034,52.405
NetLD9_K: LD9.K R55.2 | length 13.4
  Top Layer w0.204: R55.2@24.77,43.947 24.161,43.947 24.027,44.08 24.027,45.445 24.338,45.756 24.338,50.602 25.303,51.566 26.776,51.566 27.082,51.872 27.082,53.421 27.539,53.878 LD9.K@28.034,53.878
NetM1_4: M1.4 pad.85@49.23,24.363 pad.92@53.294,21.163 U1.5 | length 43.5
  Top Layer w0.204: U1.5@39.744,21.516 39.744,22.497 41.61,24.363 pad.85@49.23,24.363 ; pad.92@53.294,21.163 61.575,21.163 63.865,18.872 70.74,18.872 71.786,19.918 76.18,19.918 76.942,19.156 M1.4@76.942,18.344
  Bottom Layer w0.204: pad.85@49.23,24.363 49.23,23.195 51.262,21.163 pad.92@53.294,21.163
NetM1_7: M1.7 M2.11 M3.7 pad.42@63.708,18.013 pad.137@50.577,33.203 pad.150@23.754,36.073 pad.154 pad.160 pad.169 U1.78 | length 120
  Top Layer w0.204: M2.11@8.467,32.988 8.907,32.988 9.606,32.288 pad.154@19.004,32.288 ; pad.150@23.754,36.073 25.561,34.266 U1.78@35.994,34.266 45.653,34.266 46.716,33.203 pad.137@50.577,33.203 ; pad.42@63.708,18.013 70.77,18.013 71.43,17.353 pad.169@71.43,16.87 71.43,16.058 73.538,13.949 73.538,5.974 74.668,4.844 M1.7@75.672,4.844 ; pad.160@75.672,35.463 M3.7@75.672,36.848
  Bottom Layer w0.204: pad.154@19.004,32.288 23.17,32.288 23.729,32.847 23.729,36.047 pad.150@23.754,36.073 ; pad.137@50.577,33.203 50.983,33.203 51.491,33.711 57.562,33.711 59.898,31.374 61.676,31.374 62.694,30.357 62.694,18.801 63.481,18.013 pad.42@63.708,18.013 ; pad.169@71.43,16.87 71.43,23.5 72.979,25.049 75.443,25.049 76.053,25.659 76.053,35.082 pad.160@75.672,35.463
NetM1_8: M1.8 M2.10 M3.8 pad.21@76.688,35.26 pad.25@72.598,13.645 pad.44@62.388,16.947 pad.138 pad.149@23.297,35.641 pad.153@18.115,32.796 U1.79 | length 125
  Top Layer w0.204: M2.10@8.467,34.445 8.465,34.447 9.352,34.447 9.987,33.812 9.987,33.304 10.495,32.796 pad.153@18.115,32.796 ; pad.149@23.297,35.666 25.198,33.766 U1.79@35.994,33.766 45.645,33.766 46.64,32.771 pad.138@50.297,32.771 ; pad.44@62.388,16.947 69.296,16.947 pad.25@72.598,13.645 72.598,6.101 75.062,3.637 76.739,3.637 76.942,3.84 M1.8@76.942,4.844 ; pad.21@76.688,35.26 76.942,35.514 M3.8@76.942,36.848
  Bottom Layer w0.204: pad.153@18.115,32.796 22.992,32.796 23.297,33.101 pad.149@23.297,35.641 ; pad.138@50.297,32.796 51.149,32.796 51.631,33.279 57.435,33.279 59.721,30.993 61.549,30.993 62.388,30.155 pad.44@62.388,16.947 ; pad.25@72.598,13.645 72.598,13.949 72.673,14.024 72.673,22.127 73.537,22.99 73.537,24.108 74.172,24.743 75.747,24.743 76.688,25.684 pad.21@76.688,35.26
NetM1_9: M1.9 M2.9 M3.9 pad.22@77.399,35.235 pad.27@73.056,13.848 pad.43@62.032,17.378 pad.139 pad.161 pad.163 U1.80 | length 123.1
  Top Layer w0.204: M2.9@8.467,35.902 9.676,35.902 10.368,35.209 22.916,35.209 24.86,33.266 U1.80@35.994,33.266 45.688,33.266 46.614,32.339 pad.139@50.526,32.339 ; pad.43@62.032,17.378 69.525,17.378 pad.27@73.056,13.848 pad.161@73.056,6.431 ; pad.22@77.399,35.235 77.399,35.514 77.602,35.717 78.009,35.717 78.212,35.92 M3.9@78.212,36.848 ; pad.163@78.212,3.764 M1.9@78.212,4.844
  Bottom Layer w0.204: pad.139@50.526,32.339 51.288,32.339 51.872,32.923 57.13,32.923 59.543,30.51 61.473,30.51 62.007,29.977 pad.43@62.007,17.378 ; pad.161@73.056,6.431 73.056,5.72 75.011,3.764 pad.163@78.212,3.764 ; pad.27@73.056,13.848 73.056,21.773 73.895,22.612 73.895,23.882 74.427,24.414 76.054,24.414 77.17,25.531 77.17,35.006 pad.22@77.399,35.235
NetM1_10: M1.10 pad.198 pad.199 U1.60 | length 93.8
  Top Layer w0.204: pad.198@45.244,35.973 U1.60@45.244,37.016 ; pad.199@56.063,16.083 68.915,16.083 71.709,13.289 71.709,6.507 74.975,3.241 78.782,3.241 79.482,3.942 M1.10@79.482,4.844
  Bottom Layer w0.204: pad.198@45.244,35.973 45.244,29.242 43.771,27.768 43.771,13.974 43.312,13.515 43.312,3.586 43.998,2.9 46.462,2.9 48.773,5.212 48.773,11.943 47.884,12.832 47.884,13.492 48.164,13.772 55.504,13.772 56.063,14.33 pad.199@56.063,16.083
NetM1_11: M1.11 pad.162 pad.164 pad.191 pad.192 pad.194 pad.195 pad.196 pad.197 U1.67 | length 89.8
  Top Layer w0.204: pad.197@35.057,16.337 36.149,15.244 36.149,13.746 37.648,12.248 pad.196@49.383,12.248 ; pad.194@36.937,30.485 pad.192@40.137,30.485 ; pad.191@40.137,35.997 41.382,35.997 41.744,36.359 U1.67@41.744,37.016 ; pad.195@56.139,16.515 69.169,16.515 72.116,13.568 pad.164@72.116,6.787 ; pad.162@79.888,3.281 80.752,4.145 M1.11@80.752,4.844
  Bottom Layer w0.204: pad.197@35.057,16.337 35.057,21.772 35.997,22.712 35.997,23.881 36.632,24.516 36.632,30.18 pad.194@36.937,30.485 ; pad.192@40.137,30.485 pad.191@40.137,35.997 ; pad.196@49.383,12.248 55.631,12.248 56.774,13.391 56.774,15.88 pad.195@56.139,16.515 ; pad.164@72.116,6.787 72.116,6.05 74.935,3.231 pad.162@79.888,3.231
NetM2_4: M2.4 pad.1@6.992,43.187 TP1.1 | length 3
  Top Layer w0.204: pad.1@6.992,43.187 M2.4@8.467,43.187
  Bottom Layer w0.204: pad.1@6.992,43.187 TP1.1@8.472,43.187
NetM2_5: M2.5 pad.2@7.034,41.73 TP2.1 | length 2.9
  Top Layer w0.204: pad.2@7.034,41.73 M2.5@8.467,41.73
  Bottom Layer w0.204: pad.2@7.034,41.73 TP2.1@8.472,41.73
NetM2_6: M2.6 pad.3@6.999,40.273 TP3.1 | length 2.9
  Top Layer w0.204: pad.3@6.999,40.273 M2.6@8.467,40.273
  Bottom Layer w0.204: pad.3@6.999,40.273 TP3.1@8.472,40.273
NetM2_7: M2.7 pad.4@6.99,38.816 TP4.1 | length 3
  Top Layer w0.204: pad.4@6.99,38.816 M2.7@8.467,38.816
  Bottom Layer w0.204: pad.4@6.99,38.816 TP4.1@8.472,38.816
NetM2_8: M2.8 pad.5@7.076,37.359 TP5.1 | length 2.8
  Top Layer w0.204: pad.5@7.076,37.359 M2.8@8.467,37.359
  Bottom Layer w0.204: pad.5@7.076,37.359 TP5.1@8.472,37.359
NetM2_12: M2.12 pad.145@28.381,24.766 pad.147 R26.1 U1.97 | length 38.1
  Top Layer w0.204: R26.1@7.143,31.602 8.395,31.602 M2.12@8.467,31.531 12.786,31.531 13.035,31.78 19.385,31.78 21.29,33.685 23.5,33.685 24.465,32.72 pad.147@28.25,32.72 ; pad.145@28.381,24.766 U1.97@35.994,24.766
  Bottom Layer w0.204: pad.147@28.25,32.72 28.354,32.616 28.354,24.793 pad.145@28.381,24.766
NetM2_13: M2.13 pad.146@28,24.266 pad.148 U1.98 | length 36.5
  Top Layer w0.204: M2.13@8.467,30.074 11.964,30.074 13.244,31.354 19.492,31.354 20.427,32.288 pad.148@27.996,32.288 ; pad.146@28,24.266 U1.98@35.994,24.266
  Bottom Layer w0.204: pad.146@28,24.266 pad.148@28,32.284
NetM2_16: M2.16 pad.152@31.146,31.298 pad.155@31.146,35.184 U1.52 | length 44.3
  Top Layer w0.204: M2.16@12.507,28.874 12.507,29.896 13.451,30.84 22.891,30.84 23.348,31.298 pad.152@31.146,31.298 ; pad.155@31.146,35.184 31.171,35.209 33.508,35.209 34.016,35.717 36.911,35.717 37.646,34.982 48.368,34.982 49.244,35.858 U1.52@49.244,37.016
  Bottom Layer w0.204: pad.152@31.146,31.298 pad.155@31.146,35.184
NetM2_21: M2.21 pad.101@26.294,36.632 pad.104@26.091,27.996 U1.55 | length 40.2
  Top Layer w0.204: M2.21@19.607,28.874 19.607,28.257 19.893,27.97 pad.104@26.091,27.97 ; pad.101@26.294,36.632 31.984,36.632 34.575,39.222 46.894,39.222 47.744,38.372 U1.55@47.744,37.016
  Bottom Layer w0.204: pad.104@26.091,27.996 26.091,36.428 pad.101@26.294,36.632
NetM2_22: M2.22 pad.102@26.574,36.225 pad.103@26.574,28.859 U1.56 | length 36.1
  Top Layer w0.204: M2.22@21.027,28.874 pad.103@26.574,28.874 ; pad.102@26.574,36.225 32.212,36.225 34.904,38.916 46.336,38.916 47.244,38.008 U1.56@47.244,37.016
  Bottom Layer w0.204: pad.103@26.574,28.859 pad.102@26.574,36.225
NetM2_28: M2.28 R66.1 | length 1.3
  Top Layer w0.204: M2.28@22.227,37.359 R66.1@23.535,37.359
NetM2_29: M2.29 R64.1 R65.1 | length 2.3
  Top Layer w0.204: M2.29@22.227,38.816 23.551,38.816 ; R65.1@23.551,38.333 23.551,38.816 ; R64.1@23.551,39.299 23.551,38.816
NetM2_33: M2.33 U1.51 | length 42.2
  Top Layer w0.24: M2.33@22.227,44.644 21.533,44.644 21.189,44.988 21.189,46.385 21.646,46.842 23.043,46.842 23.627,46.258 23.627,42.22 26.142,39.705 26.142,37.8 26.964,36.978 31.721,36.978 34.346,39.603 49.103,39.603 49.744,38.963 U1.51@49.744,37.016
NetM2_34: M2.34 pad.33@33.66,34.777 pad.93@37.75,32.11 U1.39 | length 41.1
  Top Layer w0.24: M2.34@22.227,46.101 22.845,46.101 23.195,45.75 23.195,42.118 25.75,39.563 25.75,39.116 25.735,39.101 25.735,35.539 26.497,34.777 pad.33@33.66,34.777 ; pad.93@37.75,32.11 44.354,32.11 46.055,30.409 50.287,30.409 50.93,29.766 U1.39@51.494,29.766
  Bottom Layer w0.24: pad.33@33.66,34.777 33.66,33.782 35.331,32.11 pad.93@37.75,32.11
